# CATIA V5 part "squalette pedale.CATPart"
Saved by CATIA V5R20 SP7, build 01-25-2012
Part number: squalette pedale
Publications: "Longueur de la liaison", "Droite.1", "Point.1", "Plan.1", "Longueur du pedale"
Bounding box of the stored display mesh (mm): x 0 to 0, y -40 to 0, z 0 to 0
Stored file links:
  D:\thinkmotion-MPB\Dropbox\Pack 1 sylvain\CFAO_2010_yyang\yyang\CFAO_2010_yyang\squalette pedale.CATPart
  D:\thinkmotion-MPB\Dropbox\Pack 1 sylvain\CFAO_2010_yyang\yyang\CFAO_2010_yyang\yyang.CATProduct

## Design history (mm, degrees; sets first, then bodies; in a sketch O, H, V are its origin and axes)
Parameters
  `Longueur de la liaison` = 47.5 mm {= `External.rayon1 de l'antiboue`+`External.epaisseur de la boite`+10mm}
  `Longueur du pedale` = 175 mm
External parameters (linked from other documents)
  `External.rayon1 de l'antiboue` = 30 mm
  `External.epaisseur de la boite` = 7.5 mm
Set1
  Plane1: linked copy from another document
Set2
  Point1: (0, 0, 0)
  Line1: type PtDir, RefPoint Point1, Direction (0, 1, 0), Start 0, End 40
  Plane2: type Offset, RefPlane Plane1, Offset 0
Body1 (main body)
